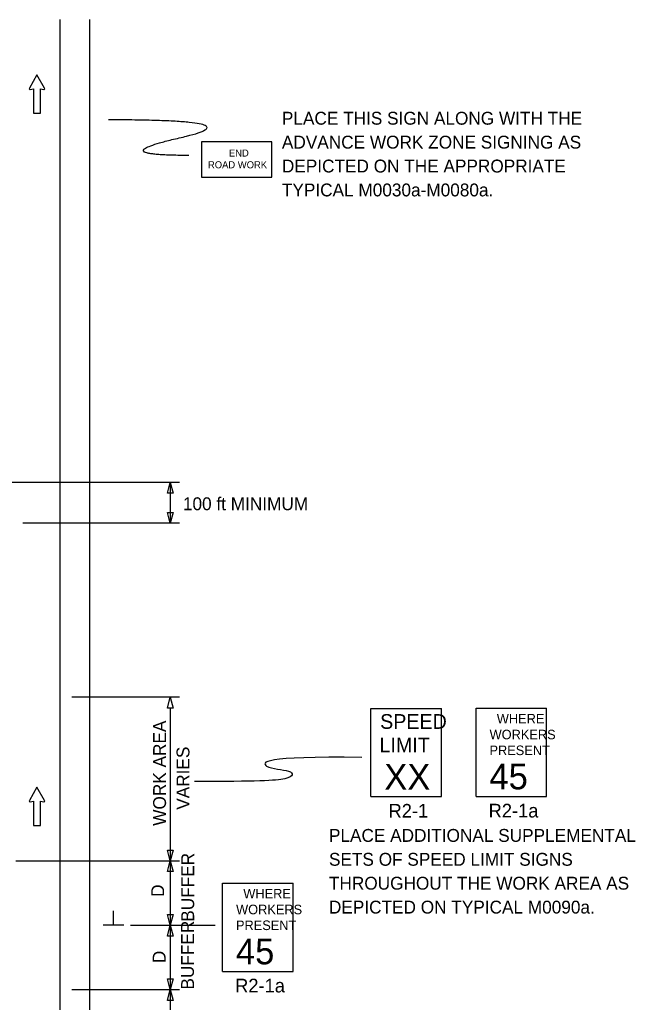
# Model space of a CAD drawing. Extents: x 16729 to 18475, y 5932 to 6920.
# Drawn here: x 17064 to 17399, y 6382 to 6916 of the extents above; entities that cross this region are included whole.
import ezdxf

# ---------------------------------------------------------------- set-up
doc = ezdxf.new("R2010")
doc.units = 0
for name, color, linetype in [('MT_SCRATCH_LEVEL_E', 7, 'Continuous'), ('PAVT_EDGE_EX', 7, 'Continuous'), ('TRAFFIC_SIGNS_PR', 7, 'Continuous'), ('TYPICAL_TEXT_DIMEN_PR', 7, 'Continuous')]:
    doc.layers.add(name, color=color, linetype=linetype)

msp = doc.modelspace()

# ---------------------------------------------------------------- linework, layer by layer
at = {"layer": 'MT_SCRATCH_LEVEL_E'}
for p, q in [((17073.64, 6886.4), (17069.53, 6879.15)), ((17073.64, 6886.4), (17069.53, 6879.15)), ((17077.78, 6879.15), (17073.64, 6886.4)), ((17077.78, 6879.15), (17073.64, 6886.4)), ((17070.01, 6878.47), (17071.79, 6878.79)), ((17070.01, 6878.47), (17071.79, 6878.79)), ((17071.79, 6878.79), (17071.79, 6865.53)), ((17071.79, 6878.79), (17071.79, 6865.53)), ((17075.53, 6865.53), (17075.53, 6878.79)), ((17075.53, 6878.79), (17077.3, 6878.47)), ((17075.53, 6865.53), (17075.53, 6878.79)), ((17075.53, 6878.79), (17077.3, 6878.47)), ((17071.79, 6865.53), (17075.53, 6865.53)), ((17071.79, 6865.53), (17075.53, 6865.53)), ((17073.64, 6498.96), (17069.53, 6491.72)), ((17073.64, 6498.96), (17069.53, 6491.72)), ((17077.78, 6491.72), (17073.64, 6498.96)), ((17077.78, 6491.72), (17073.64, 6498.96)), ((17070.01, 6491.04), (17071.79, 6491.35)), ((17070.01, 6491.04), (17071.79, 6491.35)), ((17071.79, 6491.35), (17071.79, 6478.1)), ((17071.79, 6491.35), (17071.79, 6478.1)), ((17075.53, 6478.1), (17075.53, 6491.35)), ((17075.53, 6491.35), (17077.3, 6491.04)), ((17075.53, 6478.1), (17075.53, 6491.35)), ((17075.53, 6491.35), (17077.3, 6491.04)), ((17071.79, 6478.1), (17075.53, 6478.1)), ((17071.79, 6478.1), (17075.53, 6478.1))]:
    msp.add_line(p, q, dxfattribs=at)
for centre, start, end in [((17069.93, 6878.93), 150.4248, 279.9638), ((17069.93, 6878.93), 150.4248, 279.9638), ((17077.37, 6878.93), 260.0362, 29.7731), ((17077.37, 6878.93), 260.0362, 29.7731), ((17069.93, 6491.5), 150.4248, 279.9638), ((17069.93, 6491.5), 150.4248, 279.9638), ((17077.37, 6491.5), 260.0362, 29.7731), ((17077.37, 6491.5), 260.0362, 29.7731)]:
    msp.add_arc(centre, 0.463, start, end, dxfattribs=at)
at = {"layer": 'PAVT_EDGE_EX'}
for p, q in [((17086.12, 6916.46), (17086.12, 6065.34)), ((17102.12, 6916.46), (17102.12, 6065.34))]:
    msp.add_line(p, q, dxfattribs=at)
at = {"layer": 'TRAFFIC_SIGNS_PR'}
for p, q in [((17255.27, 6541.86), (17293.67, 6541.86)), ((17255.27, 6493.86), (17255.27, 6541.86)), ((17293.67, 6493.86), (17293.67, 6541.86)), ((17312.46, 6541.94), (17350.86, 6541.94)), ((17312.46, 6493.94), (17312.46, 6541.94)), ((17350.86, 6493.94), (17350.86, 6541.94)), ((17255.27, 6493.86), (17293.67, 6493.86)), ((17312.46, 6493.94), (17350.86, 6493.94)), ((17174.57, 6446.79), (17212.97, 6446.79)), ((17174.57, 6398.79), (17174.57, 6446.79)), ((17212.97, 6398.79), (17212.97, 6446.79)), ((17174.57, 6398.79), (17212.97, 6398.79))]:
    msp.add_line(p, q, dxfattribs=at)
msp.add_lwpolyline([(17163.04, 6830.87), (17201.44, 6830.87), (17201.44, 6850.07), (17163.04, 6850.07)], close=True, dxfattribs=at)
msp.add_open_spline([(17156.32, 6842.6), (17109.08, 6842.6), (17194.11, 6861.95), (17112.63, 6861.95)], degree=2, dxfattribs=at)
at = {"layer": 'TYPICAL_TEXT_DIMEN_PR'}
for p, q in [((17151.12, 6664.74), (17041.37, 6664.74)), ((17144.55, 6658.87), (17146.12, 6664.74)), ((17146.12, 6664.74), (17146.12, 6642.54)), ((17146.12, 6664.74), (17147.69, 6658.87)), ((17146.12, 6658.87), (17144.55, 6658.87)), ((17147.69, 6658.87), (17146.12, 6658.87)), ((17146.12, 6642.54), (17144.55, 6648.4)), ((17144.55, 6648.4), (17146.12, 6648.4)), ((17146.12, 6648.4), (17147.69, 6648.4)), ((17147.69, 6648.4), (17146.12, 6642.54)), ((17151.12, 6642.54), (17065.98, 6642.54)), ((17151.12, 6547.86), (17092.66, 6547.86)), ((17144.55, 6542), (17146.12, 6547.86)), ((17146.12, 6547.86), (17147.69, 6542)), ((17146.12, 6542), (17144.55, 6542)), ((17147.69, 6542), (17146.12, 6542)), ((17146.12, 6541.89), (17146.12, 6458.9)), ((17146.12, 6458.9), (17144.55, 6464.76)), ((17144.55, 6464.76), (17146.12, 6464.76)), ((17146.12, 6464.76), (17147.69, 6464.76)), ((17147.69, 6464.76), (17146.12, 6458.9)), ((17062.12, 6458.9), (17151.12, 6458.9)), ((17144.55, 6453.04), (17146.12, 6458.9)), ((17146.12, 6458.9), (17147.69, 6453.04)), ((17146.12, 6458.9), (17146.12, 6423.9)), ((17146.12, 6453.04), (17144.55, 6453.04)), ((17147.69, 6453.04), (17146.12, 6453.04)), ((17115.2, 6423.95), (17115.2, 6431.73)), ((17146.12, 6423.9), (17144.55, 6429.76)), ((17144.55, 6429.76), (17146.12, 6429.76)), ((17146.12, 6429.76), (17147.69, 6429.76)), ((17147.69, 6429.76), (17146.12, 6423.9)), ((17120.82, 6423.95), (17109.57, 6423.95)), ((17124.45, 6423.9), (17170.59, 6423.9)), ((17144.55, 6418.04), (17146.12, 6423.9)), ((17146.12, 6423.9), (17147.69, 6418.04)), ((17146.12, 6423.9), (17146.12, 6388.9)), ((17146.12, 6418.04), (17144.55, 6418.04)), ((17147.69, 6418.04), (17146.12, 6418.04)), ((17146.12, 6388.9), (17144.55, 6394.76)), ((17144.55, 6394.76), (17146.12, 6394.76)), ((17146.12, 6394.76), (17147.69, 6394.76)), ((17147.69, 6394.76), (17146.12, 6388.9)), ((17092.66, 6388.9), (17151.12, 6388.9)), ((17092.66, 6388.9), (17151.12, 6388.9)), ((17144.55, 6383.04), (17146.12, 6388.9)), ((17146.12, 6388.9), (17146.12, 6356.65)), ((17146.12, 6388.9), (17147.69, 6383.04)), ((17146.12, 6383.04), (17144.55, 6383.04)), ((17147.69, 6383.04), (17146.12, 6383.04))]:
    msp.add_line(p, q, dxfattribs=at)
msp.add_open_spline([(17250.42, 6515.19), (17195.57, 6515.92), (17195.57, 6508.68), (17213.46, 6508.68), (17213.46, 6502.82), (17193.42, 6502.03), (17159.27, 6502.1)], degree=3, dxfattribs=at)

# ---------------------------------------------------------------- texts
at = {"layer": 'TRAFFIC_SIGNS_PR'}
for s, height, p in [('PLACE THIS SIGN ALONG WITH THE', 7, (17206.87, 6859.33)), ('ADVANCE WORK ZONE SIGNING AS', 7, (17206.87, 6846.33)), ('END', 3.831, (17178.05, 6842)), ('ROAD WORK', 3.831, (17166.65, 6835.61)), ('DEPICTED ON THE APPROPRIATE', 7, (17206.87, 6833.33)), ('TYPICAL M0030a-M0080a.', 7, (17206.87, 6820.33)), ('SPEED', 8, (17260.3, 6530.72)), ('WHERE', 5.2, (17323.77, 6533.63)), ('WORKERS', 5.2, (17319.85, 6525.03)), ('LIMIT', 8, (17259.97, 6517.92)), ('PRESENT', 5.2, (17319.78, 6516.43)), ('XX', 14.031, (17262.57, 6497.61)), ('45', 14.031, (17319.77, 6497.8)), ('R2-1', 7.44, (17264.88, 6482.42)), ('R2-1a', 7.44, (17319.32, 6482.5)), ('PLACE ADDITIONAL SUPPLEMENTAL', 7, (17232.46, 6469.25)), ('SETS OF SPEED LIMIT SIGNS', 7, (17232.46, 6456.25)), ('THROUGHOUT THE WORK AREA AS', 7, (17232.46, 6443.25)), ('WHERE', 5.2, (17185.88, 6438.47)), ('DEPICTED ON TYPICAL M0090a.', 7, (17232.46, 6430.25)), ('WORKERS', 5.2, (17181.95, 6429.87)), ('PRESENT', 5.2, (17181.88, 6421.27)), ('45', 14.031, (17181.87, 6402.64)), ('R2-1a', 7.44, (17181.42, 6387.35))]:
    msp.add_text(s, height=height, dxfattribs=at).set_placement(p)
at = {"layer": 'TYPICAL_TEXT_DIMEN_PR'}
msp.add_text('100 ft MINIMUM', height=7, dxfattribs=at).set_placement((17153.02, 6649.64))
for s, p in [('WORK AREA', (17143.83, 6477.99)), ('VARIES', (17156.57, 6486.71)), ('BUFFER', (17159.15, 6425.81)), ('D', (17142.8, 6439.32)), ('BUFFER', (17159.03, 6388.9)), ('D', (17143.59, 6403.26))]:
    msp.add_text(s, height=7, rotation=90, dxfattribs=at).set_placement(p)

doc.saveas('drawing.dxf')
